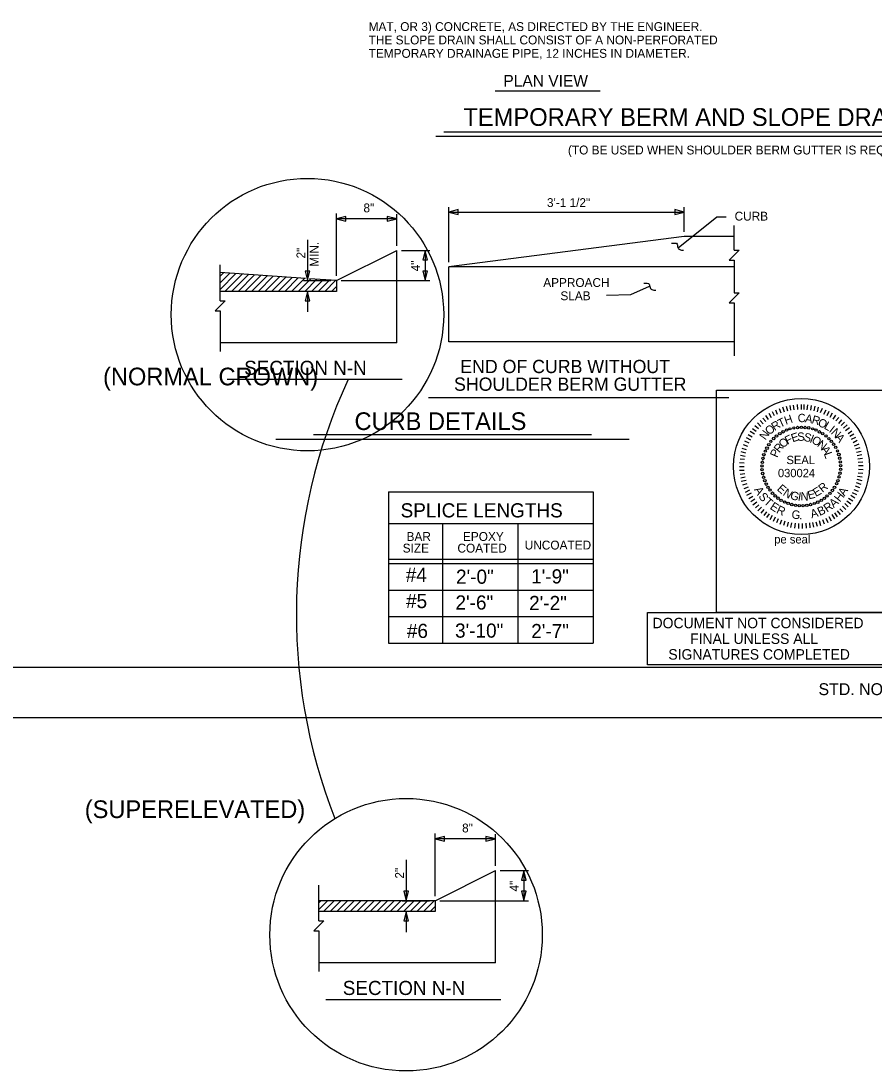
# Model space of a CAD drawing. Extents: x -151 to 116, y -17 to 117.
# Drawn here: x 62.29 to 98.16, y -14.85 to 29.29 of the extents above; entities that cross this region are included whole.
import ezdxf

# ---------------------------------------------------------------- set-up
doc = ezdxf.new("R2010")
doc.units = 0
for name, color, linetype in [('Arrowhead Terminators CELL', 7, 'Continuous'), ('Dimension Lines', 7, 'Continuous'), ('Mis Object Lines', 7, 'Continuous'), ('Peseal', 7, 'Continuous'), ('Plan Sheet', 7, 'Continuous'), ('Plot Shape', 7, 'Continuous'), ('Sheet Sticker Exception Certification CELL', 7, 'Continuous'), ('Subtitle Text', 7, 'Continuous'), ('Text', 7, 'Continuous'), ('Title Text', 7, 'Continuous'), ('User Information Notes', 7, 'Continuous'), ('User Information Notes CELL', 7, 'Continuous')]:
    doc.layers.add(name, color=color, linetype=linetype)

msp = doc.modelspace()

# ---------------------------------------------------------------- linework, layer by layer
at = {"layer": 'Arrowhead Terminators CELL'}
for points in [[(80.279, 21.263), (80.675, 21.164), (80.675, 21.362)], [(90.179, 21.263), (89.783, 21.362), (89.783, 21.164)], [(75.552, 20.977), (75.948, 20.878), (75.948, 21.076)], [(78.086, 20.977), (77.69, 21.076), (77.69, 20.878)], [(79.28, 19.645), (79.181, 19.249), (79.379, 19.249)], [(74.336, 18.378), (74.435, 18.774), (74.237, 18.774)], [(79.28, 18.378), (79.379, 18.774), (79.181, 18.774)], [(74.336, 17.927), (74.237, 17.531), (74.435, 17.531)], [(79.698, -5.091), (80.094, -5.19), (80.094, -4.992)], [(82.233, -5.091), (81.837, -4.992), (81.837, -5.19)], [(83.427, -6.423), (83.328, -6.819), (83.526, -6.819)], [(78.483, -7.69), (78.582, -7.294), (78.384, -7.294)], [(83.427, -7.69), (83.526, -7.294), (83.328, -7.294)], [(78.483, -8.141), (78.384, -8.537), (78.582, -8.537)]]:
    msp.add_lwpolyline(points, close=True, dxfattribs=at)
at = {"layer": 'Dimension Lines'}
for p, q in [((75.552, 18.576), (75.552, 21.201)), ((80.279, 19.16), (80.279, 21.461)), ((80.279, 21.263), (90.179, 21.263)), ((90.179, 20.427), (90.179, 21.461)), ((78.086, 20.977), (75.552, 20.977)), ((78.086, 19.843), (78.086, 21.179)), ((74.336, 20.099), (74.336, 18.378)), ((78.284, 19.645), (79.478, 19.645)), ((79.28, 19.645), (79.28, 18.378)), ((74.162, 18.378), (75.318, 18.378)), ((75.75, 18.378), (79.478, 18.378)), ((87.923, 17.792), (88.718, 18.139)), ((74.336, 17.927), (74.336, 17.063)), ((86.905, 17.772), (87.923, 17.792)), ((70.962, 14.231), (78.311, 14.231)), ((79.698, -7.492), (79.698, -4.867)), ((82.233, -5.091), (79.698, -5.091)), ((82.233, -6.225), (82.233, -4.89)), ((78.483, -5.969), (78.483, -7.69)), ((82.431, -6.423), (83.625, -6.423)), ((83.427, -6.423), (83.427, -7.69)), ((78.309, -7.69), (79.465, -7.69)), ((79.896, -7.69), (83.625, -7.69)), ((78.483, -8.141), (78.483, -9.005)), ((75.108, -11.837), (82.457, -11.837))]:
    msp.add_line(p, q, dxfattribs=at)
msp.add_lwpolyline([(89.926, 19.755), (91.546, 21.055), (91.942, 21.055)], dxfattribs=at)
for points in [[(89.646, 19.951), (89.879, 19.915), (89.896, 19.808), (89.986, 19.683), (90.147, 19.665)], [(88.475, 18.269), (88.707, 18.233), (88.725, 18.126), (88.814, 18.001), (88.975, 17.983)]]:
    msp.add_spline(points, degree=3, dxfattribs=at)
at = {"layer": 'Mis Object Lines'}
for p, q in [((92.281, 19.654), (92.281, 20.701)), ((90.179, 20.229), (80.279, 18.962)), ((92.281, 20.229), (90.179, 20.229)), ((75.552, 18.378), (78.086, 19.645)), ((78.086, 15.762), (78.086, 19.645)), ((70.663, 17.53), (70.663, 19.038)), ((78.086, 15.762), (78.086, 19.186)), ((92.28, 19.235), (92.28, 17.863)), ((70.644, 18.27), (71.065, 18.692)), ((74.247, 18.469), (70.663, 18.72)), ((70.663, 18.57), (70.804, 18.71)), ((70.663, 18.01), (71.327, 18.673)), ((70.861, 17.927), (71.589, 18.655)), ((71.141, 17.927), (71.85, 18.637)), ((71.421, 17.927), (72.112, 18.618)), ((71.701, 17.927), (72.374, 18.6)), ((71.981, 17.927), (72.636, 18.582)), ((72.261, 17.927), (72.897, 18.564)), ((72.541, 17.927), (73.159, 18.545)), ((80.279, 15.802), (80.279, 18.962)), ((92.281, 18.962), (80.279, 18.962)), ((72.821, 17.927), (73.421, 18.527)), ((73.101, 17.927), (73.682, 18.509)), ((73.381, 17.927), (73.944, 18.49)), ((73.661, 17.927), (74.206, 18.472)), ((73.941, 17.927), (74.468, 18.454)), ((74.221, 17.927), (74.729, 18.435)), ((75.552, 18.378), (74.416, 18.457)), ((74.501, 17.927), (74.991, 18.417)), ((74.781, 17.927), (75.253, 18.399)), ((75.061, 17.927), (75.514, 18.381)), ((75.341, 17.927), (75.552, 18.138)), ((75.552, 18.378), (75.552, 17.927)), ((75.552, 17.927), (70.663, 17.927)), ((92.279, 17.444), (92.279, 15.217)), ((70.662, 17.109), (70.662, 15.401)), ((78.086, 15.762), (70.662, 15.762)), ((92.279, 15.802), (80.279, 15.802)), ((79.698, -7.69), (82.233, -6.423)), ((82.233, -10.306), (82.233, -6.423)), ((74.81, -8.538), (74.81, -7.03)), ((82.233, -10.306), (82.233, -6.882)), ((74.81, -7.779), (74.898, -7.69)), ((74.81, -8.059), (75.178, -7.69)), ((79.698, -7.69), (74.81, -7.69)), ((75.007, -8.141), (75.458, -7.69)), ((75.287, -8.141), (75.738, -7.69)), ((75.567, -8.141), (76.018, -7.69)), ((75.847, -8.141), (76.298, -7.69)), ((76.127, -8.141), (76.578, -7.69)), ((76.407, -8.141), (76.858, -7.69)), ((76.687, -8.141), (77.138, -7.69)), ((76.967, -8.141), (77.418, -7.69)), ((77.247, -8.141), (77.698, -7.69)), ((77.527, -8.141), (77.978, -7.69)), ((77.807, -8.141), (78.258, -7.69)), ((78.087, -8.141), (78.538, -7.69)), ((78.367, -8.141), (78.818, -7.69)), ((78.647, -8.141), (79.098, -7.69)), ((78.927, -8.141), (79.378, -7.69)), ((79.207, -8.141), (79.658, -7.69)), ((79.487, -8.141), (79.698, -7.93)), ((79.698, -7.69), (79.698, -8.141)), ((79.698, -8.141), (74.81, -8.141)), ((74.809, -8.959), (74.809, -10.668)), ((82.233, -10.306), (74.809, -10.306))]:
    msp.add_line(p, q, dxfattribs=at)
for points in [[(92.281, 19.654), (92.49, 19.654), (92.071, 19.235), (92.28, 19.235)], [(92.28, 17.863), (92.489, 17.863), (92.07, 17.444), (92.279, 17.444)], [(70.663, 17.53), (70.873, 17.53), (70.452, 17.109), (70.662, 17.109)], [(74.81, -8.538), (75.02, -8.538), (74.599, -8.959), (74.809, -8.959)]]:
    msp.add_lwpolyline(points, dxfattribs=at)
at = {"layer": 'Peseal'}
for p, q in [((93.975, 12.69), (93.887, 12.865)), ((94.1, 12.753), (94.025, 12.928)), ((94.25, 12.803), (94.175, 12.99)), ((94.387, 12.853), (94.325, 13.053)), ((94.525, 12.89), (94.475, 13.09)), ((94.662, 12.928), (94.625, 13.128)), ((94.8, 12.94), (94.775, 13.14)), ((94.95, 12.965), (94.937, 13.165)), ((95.1, 12.965), (95.1, 13.165)), ((95.212, 12.965), (95.225, 13.165)), ((95.35, 12.953), (95.375, 13.153)), ((95.5, 12.928), (95.525, 13.128)), ((95.637, 12.903), (95.675, 13.103)), ((95.775, 12.865), (95.825, 13.065)), ((95.912, 12.828), (95.987, 13.015)), ((96.05, 12.765), (96.137, 12.953)), ((96.187, 12.703), (96.275, 12.89)), ((96.312, 12.64), (96.412, 12.815)), ((93.4, 12.253), (93.25, 12.403)), ((93.5, 12.353), (93.375, 12.503)), ((93.612, 12.453), (93.487, 12.603)), ((93.725, 12.54), (93.612, 12.703)), ((93.85, 12.615), (93.75, 12.79)), ((96.437, 12.553), (96.55, 12.728)), ((96.55, 12.478), (96.675, 12.628)), ((96.675, 12.378), (96.8, 12.528)), ((96.775, 12.29), (96.912, 12.428)), ((93.125, 11.928), (92.95, 12.04)), ((93.2, 12.04), (93.05, 12.153)), ((93.3, 12.153), (93.15, 12.278)), ((96.875, 12.178), (97.025, 12.315)), ((96.962, 12.078), (97.125, 12.203)), ((97.062, 11.953), (97.225, 12.065)), ((97.137, 11.84), (97.3, 11.94)), ((92.85, 11.403), (92.662, 11.478)), ((92.912, 11.54), (92.725, 11.628)), ((92.975, 11.665), (92.787, 11.765)), ((93.037, 11.803), (92.862, 11.903)), ((97.212, 11.715), (97.387, 11.803)), ((97.275, 11.578), (97.45, 11.665)), ((97.337, 11.44), (97.525, 11.515)), ((92.762, 11.128), (92.575, 11.178)), ((92.8, 11.265), (92.612, 11.328)), ((97.387, 11.303), (97.575, 11.365)), ((97.425, 11.165), (97.612, 11.215)), ((97.45, 11.028), (97.65, 11.065)), ((92.7, 10.703), (92.5, 10.715)), ((92.712, 10.853), (92.525, 10.878)), ((92.737, 10.99), (92.537, 11.028)), ((97.475, 10.89), (97.675, 10.915)), ((97.487, 10.753), (97.687, 10.765)), ((97.5, 10.603), (97.7, 10.603)), ((92.7, 10.553), (92.5, 10.553)), ((92.7, 10.403), (92.5, 10.39)), ((92.725, 10.253), (92.525, 10.228)), ((97.462, 10.165), (97.662, 10.128)), ((97.487, 10.303), (97.687, 10.278)), ((97.5, 10.453), (97.7, 10.44)), ((92.737, 10.115), (92.55, 10.078)), ((92.775, 9.978), (92.575, 9.928)), ((92.812, 9.84), (92.625, 9.778)), ((97.362, 9.753), (97.55, 9.678)), ((97.4, 9.89), (97.6, 9.828)), ((97.437, 10.028), (97.637, 9.978)), ((92.862, 9.703), (92.675, 9.628)), ((92.925, 9.565), (92.737, 9.478)), ((92.987, 9.44), (92.8, 9.34)), ((93.062, 9.303), (92.887, 9.203)), ((97.175, 9.353), (97.35, 9.253)), ((97.237, 9.478), (97.425, 9.39)), ((97.3, 9.603), (97.487, 9.528)), ((93.137, 9.19), (92.975, 9.078)), ((93.225, 9.065), (93.062, 8.94)), ((93.312, 8.953), (93.175, 8.828)), ((93.425, 8.853), (93.275, 8.703)), ((96.825, 8.903), (96.975, 8.753)), ((96.925, 9.003), (97.075, 8.865)), ((97.012, 9.115), (97.175, 8.99)), ((97.087, 9.228), (97.262, 9.115)), ((93.525, 8.753), (93.4, 8.603)), ((93.637, 8.653), (93.525, 8.503)), ((93.75, 8.578), (93.637, 8.415)), ((93.875, 8.503), (93.775, 8.328)), ((94, 8.428), (93.912, 8.253)), ((96.125, 8.39), (96.212, 8.215)), ((96.25, 8.465), (96.35, 8.278)), ((96.375, 8.54), (96.487, 8.365)), ((96.5, 8.615), (96.612, 8.453)), ((96.612, 8.703), (96.737, 8.54)), ((96.725, 8.79), (96.85, 8.653)), ((94.125, 8.365), (94.05, 8.19)), ((94.262, 8.315), (94.2, 8.128)), ((94.412, 8.265), (94.35, 8.078)), ((94.55, 8.228), (94.5, 8.04)), ((94.687, 8.203), (94.65, 8.003)), ((94.837, 8.178), (94.812, 7.978)), ((94.987, 8.165), (94.975, 7.965)), ((95.137, 8.165), (95.137, 7.965)), ((95.287, 8.178), (95.3, 7.978)), ((95.437, 8.19), (95.462, 7.99)), ((95.575, 8.215), (95.612, 8.015)), ((95.712, 8.24), (95.762, 8.053)), ((95.85, 8.29), (95.912, 8.09)), ((95.987, 8.34), (96.062, 8.153))]:
    msp.add_line(p, q, dxfattribs=at)
for centre, radius in [((94.194, 11.946), 0.0538), ((94.337, 12.028), 0.0559), ((94.481, 12.096), 0.0476), ((94.625, 12.146), 0.0455), ((94.781, 12.184), 0.0442), ((94.944, 12.203), 0.0504), ((95.1, 12.215), 0.05), ((95.256, 12.203), 0.0504), ((95.412, 12.19), 0.0515), ((95.575, 12.146), 0.0455), ((95.719, 12.096), 0.0476), ((95.862, 12.021), 0.0504), ((96, 11.946), 0.0504), ((93.731, 11.484), 0.0538), ((93.819, 11.621), 0.0442), ((93.937, 11.74), 0.053), ((94.056, 11.846), 0.0538), ((96.131, 11.853), 0.0488), ((96.256, 11.74), 0.0488), ((96.362, 11.621), 0.0488), ((96.456, 11.503), 0.0504), ((93.525, 11.059), 0.0534), ((93.581, 11.209), 0.0476), ((93.656, 11.34), 0.0576), ((96.544, 11.365), 0.0504), ((96.619, 11.221), 0.0476), ((96.675, 11.071), 0.0534), ((93.45, 10.59), 0.05), ((93.462, 10.746), 0.0504), ((93.487, 10.903), 0.0515), ((96.712, 10.915), 0.0515), ((96.737, 10.759), 0.0504), ((96.75, 10.603), 0.05), ((93.45, 10.434), 0.0504), ((93.475, 10.271), 0.0504), ((93.512, 10.115), 0.0515), ((96.687, 10.128), 0.0515), ((96.725, 10.284), 0.0504), ((96.75, 10.446), 0.0504), ((93.562, 9.971), 0.0534), ((93.625, 9.828), 0.0559), ((93.694, 9.69), 0.0504), ((96.494, 9.69), 0.0504), ((96.581, 9.84), 0.0504), ((96.637, 9.971), 0.0534), ((93.787, 9.571), 0.0488), ((93.887, 9.44), 0.053), ((94, 9.328), 0.053), ((94.119, 9.234), 0.0538), ((96.069, 9.228), 0.0488), ((96.181, 9.328), 0.0488), ((96.3, 9.434), 0.0488), ((96.406, 9.559), 0.0538), ((94.25, 9.146), 0.0504), ((94.394, 9.071), 0.0476), ((94.544, 9.015), 0.0534), ((94.7, 8.965), 0.0515), ((94.856, 8.928), 0.0504), ((95.012, 8.915), 0.05), ((95.175, 8.915), 0.05), ((95.331, 8.928), 0.0504), ((95.487, 8.965), 0.0515), ((95.644, 9.009), 0.0476), ((95.787, 9.065), 0.0559), ((95.937, 9.146), 0.0504)]:
    msp.add_circle(centre, radius, dxfattribs=at)
at = {"layer": 'Plan Sheet'}
for p, q in [((77.743, 9.499), (86.347, 9.499)), ((77.743, 9.499), (77.743, 3.138)), ((86.347, 9.499), (86.347, 3.138)), ((77.743, 8.165), (86.347, 8.165)), ((80.017, 8.165), (80.017, 3.138)), ((83.182, 8.165), (83.182, 3.138)), ((77.743, 6.676), (86.347, 6.676)), ((77.743, 6.49), (86.347, 6.49)), ((77.743, 5.373), (86.347, 5.373)), ((77.743, 4.255), (86.347, 4.255)), ((77.743, 3.138), (86.347, 3.138)), ((3.71, 2.134), (116.351, 2.134))]:
    msp.add_line(p, q, dxfattribs=at)
at = {"layer": 'Plot Shape'}
msp.add_lwpolyline([(0, 77.44), (116.382, 77.44), (116.382, 0), (0, 0)], close=True, dxfattribs=at)
at = {"layer": 'Sheet Sticker Exception Certification CELL'}
msp.add_lwpolyline([(88.637, 4.428), (98.664, 4.428), (98.664, 2.222), (88.637, 2.222)], close=True, dxfattribs=at)
at = {"layer": 'Subtitle Text'}
msp.add_line((79.416, 13.469), (92.05, 13.469), dxfattribs=at)
at = {"layer": 'Text'}
for p, q in [((82.229, 26.356), (86.646, 26.356)), ((79.727, 24.458), (109.622, 24.458)), ((80.07, 24.632), (108.478, 24.632))]:
    msp.add_line(p, q, dxfattribs=at)
at = {"layer": 'Title Text'}
for p, q in [((87.859, 11.7), (72.998, 11.7)), ((86.275, 11.899), (74.582, 11.899))]:
    msp.add_line(p, q, dxfattribs=at)
at = {"layer": 'User Information Notes'}
msp.add_line((95.1, 10.565), (95.1, 10.565), dxfattribs=at)
for centre in [(74.332, 16.949), (78.478, -9.119)]:
    msp.add_circle(centre, 5.728, dxfattribs=at)
msp.add_arc((97.407, 4.335), 23.541, 155.224, 201.3544, dxfattribs=at)
at = {"layer": 'User Information Notes CELL'}
msp.add_line((95.1, 10.565), (95.1, 10.565), dxfattribs=at)
msp.add_lwpolyline([(91.536, 13.777), (98.664, 13.777), (98.664, 4.428), (91.536, 4.428)], close=True, dxfattribs=at)
msp.add_circle((95.1, 10.565), 2.86, dxfattribs=at)

# ---------------------------------------------------------------- texts
at = {"layer": 'Peseal'}
for s, height, rotation, p in [('R', 0.35, 32.9699, (93.975, 12.053)), ('T', 0.35, 25.943, (94.212, 12.19)), ('H', 0.35, 18.9162, (94.45, 12.315)), ('C', 0.35, 4.8625, (94.962, 12.415)), ('A', 0.35, 350.8088, (95.237, 12.428)), ('R', 0.35, 343.7819, (95.512, 12.39)), ('O', 0.35, 336.7551, (95.762, 12.29)), ('L', 0.35, 329.7282, (96.025, 12.178)), ('N', 0.35, 54.0504, (93.587, 11.653)), ('O', 0.35, 39.9967, (93.75, 11.865)), ('E', 0.35, 18.4448, (94.737, 11.578)), ('S', 0.35, 2.3789, (94.937, 11.64)), ('S', 0.35, 346.313, (95.175, 11.653)), ('I', 0.35, 322.7014, (96.237, 12.04)), ('N', 0.35, 315.6745, (96.325, 11.965)), ('R', 0.35, 50.5765, (94.175, 11.115)), ('O', 0.35, 42.5436, (94.337, 11.315)), ('F', 0.35, 26.4777, (94.512, 11.478)), ('I', 0.35, 338.28, (95.425, 11.59)), ('O', 0.35, 330.2471, (95.5, 11.578)), ('N', 0.35, 322.2141, (95.737, 11.428)), ('A', 0.35, 308.6477, (96.5, 11.778)), ('P', 0.35, 66.6424, (94.087, 10.915)), ('A', 0.35, 306.1483, (95.912, 11.278)), ('L', 0.35, 290.0824, (96.037, 11.103)), ('E', 0.35, 318.5179, (94.05, 9.59)), ('E', 0.35, 30.6815, (95.712, 9.278)), ('R', 0.35, 38.6997, (95.987, 9.453)), ('A', 0.355, 300.3993, (93.101, 9.595)), ('S', 0.355, 309.4349, (93.278, 9.293)), ('T', 0.355, 318.1096, (93.491, 9.033)), ('N', 0.35, 326.5361, (94.3, 9.378)), ('G', 0.35, 342.5725, (94.6, 9.215)), ('I', 0.35, 350.5906, (94.937, 9.14)), ('N', 0.35, 358.6088, (95.062, 9.14)), ('E', 0.35, 14.6452, (95.412, 9.178)), ('H', 0.355, 51.3597, (96.721, 9.045)), ('A', 0.355, 59.6007, (96.922, 9.293)), ('E', 0.355, 327.1453, (93.751, 8.799)), ('R', 0.355, 335.458, (94.021, 8.622)), ('B', 0.355, 24.8312, (95.872, 8.481)), ('R', 0.355, 33.5776, (96.18, 8.623)), ('A', 0.355, 42.3241, (96.462, 8.81)), ('G', 0.355, 353.3858, (94.671, 8.385)), ('.', 0.355, 2.1323, (95.008, 8.345)), ('A', 0.355, 15.7955, (95.535, 8.386))]:
    msp.add_text(s, height=height, rotation=rotation, dxfattribs=at).set_placement(p)
for s, p in [('SEAL', (94.475, 10.665)), ('030024', (94.116, 10.115))]:
    msp.add_text(s, height=0.35, dxfattribs=at).set_placement(p)
at = {"layer": 'Plan Sheet'}
for s, height, p in [('SPLICE LENGTHS', 0.59583, (78.248, 8.424)), ('BAR', 0.3724, (78.499, 7.436)), ('EPOXY ', 0.3724, (80.87, 7.436)), ('SIZE', 0.3724, (78.336, 6.947)), ('COATED', 0.3724, (80.638, 6.947)), ('UNCOATED', 0.3724, (83.467, 7.076)), ('#4', 0.5958, (78.466, 5.714)), ('2\'-0"', 0.5958, (80.579, 5.634)), ('1\'-9"', 0.5958, (83.738, 5.648)), ('#5', 0.5958, (78.478, 4.611)), ('2\'-6"', 0.5958, (80.557, 4.55)), ('2\'-2"', 0.5958, (83.653, 4.529)), ('3\'-10"', 0.5958, (80.539, 3.369)), ('#6', 0.5958, (78.513, 3.357)), ('2\'-7"', 0.5958, (83.742, 3.349))]:
    msp.add_text(s, height=height, dxfattribs=at).set_placement(p)
at = {"layer": 'Sheet Sticker Exception Certification CELL'}
for s, p in [('DOCUMENT NOT CONSIDERED', (88.843, 3.765)), ('FINAL UNLESS ALL', (90.421, 3.106)), ('SIGNATURES COMPLETED', (89.507, 2.448))]:
    msp.add_text(s, height=0.43902, dxfattribs=at).set_placement(p)
at = {"layer": 'Text'}
for s, height, p in [('MAT, OR 3) CONCRETE, AS DIRECTED BY THE ENGINEER.', 0.3727, (76.904, 28.871)), ('THE SLOPE DRAIN SHALL CONSIST OF A NON-PERFORATED', 0.3727, (76.904, 28.309)), ('TEMPORARY DRAINAGE PIPE, 12 INCHES IN DIAMETER.', 0.3727, (76.904, 27.746)), ('PLAN VIEW', 0.4887, (82.57, 26.537)), ('TEMPORARY BERM AND SLOPE DRAIN DETAILS', 0.74541, (80.888, 24.883)), ('(TO BE USED WHEN SHOULDER BERM GUTTER IS REQUIRED)', 0.37272, (85.285, 23.683)), ('3\'-1 1/2"', 0.3712, (84.403, 21.473)), ('8"', 0.3712, (76.687, 21.25)), ('CURB', 0.3712, (92.294, 20.903)), ('APPROACH', 0.3712, (84.248, 18.113)), ('SLAB', 0.3712, (84.969, 17.556)), ('SECTION N-N', 0.59251, (71.672, 14.416)), ('END OF CURB WITHOUT', 0.55737, (80.758, 14.491)), ('SHOULDER BERM GUTTER', 0.55737, (80.495, 13.748)), ('STD. NO. BAS_BB_33_90S', 0.5, (95.822, 0.954)), ('8"', 0.3712, (80.834, -4.818)), ('SECTION N-N', 0.59251, (75.818, -11.652))]:
    msp.add_text(s, height=height, dxfattribs=at).set_placement(p)
for s, p in [('MIN.', (74.801, 18.964)), ('2"', (74.243, 19.309)), ('4"', (79.063, 18.769)), ('2"', (78.39, -6.759)), ('4"', (83.209, -7.299))]:
    msp.add_text(s, height=0.3712, rotation=90, dxfattribs=at).set_placement(p)
at = {"layer": 'Title Text'}
msp.add_text('CURB DETAILS', height=0.7425, dxfattribs=at).set_placement((76.31, 12.099))
at = {"layer": 'User Information Notes'}
for s, p in [('(NORMAL CROWN)', (65.737, 13.977)), ('(SUPERELEVATED)', (64.968, -4.214))]:
    msp.add_text(s, height=0.7425, dxfattribs=at).set_placement(p)
at = {"layer": 'User Information Notes CELL'}
msp.add_text('pe seal', height=0.352, dxfattribs=at).set_placement((93.959, 7.329))

doc.saveas('drawing.dxf')
